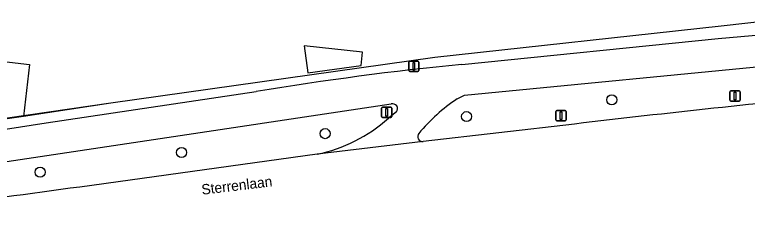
# Model space of a CAD drawing. Extents: x 162398 to 163643, y 386453 to 387397.
# Drawn here: x 163024.9 to 163096.1, y 386504.5 to 386525.7 of the extents above; entities that cross this region are included whole.
import ezdxf

# ---------------------------------------------------------------- set-up
doc = ezdxf.new("R2010")
doc.units = 0
for name, color, linetype in [('IMGEO_Boom', 7, 'Continuous'), ('IMGEO_Fietspad_gesloten', 7, 'Continuous'), ('IMGEO_Groenvoorziening', 7, 'Continuous'), ('IMGEO_Muur', 7, 'Continuous'), ('IMGEO_Openbare_ruimte_label', 7, 'Continuous'), ('IMGEO_Pand', 7, 'Continuous'), ('IMGEO_Rijbaan_regionaal_gesloten', 7, 'Continuous'), ('IMGEO_Verkeersbordpaal', 7, 'Continuous')]:
    doc.layers.add(name, color=color, linetype=linetype)

msp = doc.modelspace()

# ---------------------------------------------------------------- linework, layer by layer
at = {"layer": 'IMGEO_Boom'}
for centre in [(163082.944, 386517.469), (163068.839, 386515.839), (163055.088, 386514.185), (163041.148, 386512.357), (163027.399, 386510.439)]:
    msp.add_circle(centre, 0.489, dxfattribs=at)
at = {"layer": 'IMGEO_Fietspad_gesloten'}
for points in [[(163068.381, 386520.901), (163093.275, 386523.436), (163115.339, 386525.357)], [(163067.923, 386517.561), (163068.628, 386517.907), (163100.034, 386520.946), (163110.988, 386521.896)], [(162974.515, 386506.796), (162980.409, 386507.615), (163001.325, 386511.092), (163027.988, 386515.245), (163048.408, 386518.26)], [(162980.856, 386504.506), (162981.406, 386504.589), (162981.956, 386504.674), (163009.447, 386509.267), (163061.515, 386517.072)], [(163062.026, 386516.295), (163061.24, 386515.671)]]:
    msp.add_lwpolyline(points, dxfattribs=at)
for centre, radius, start, end in [((163096.399, 386232.165), 290.092, 95.54245, 99.52243), ((163078.016, 386502.57), 18.072, 123.95183, 139.90713), ((163061.642, 386516.599), 0.49, 321.66967, 104.99278), ((163051.071, 386527.234), 15.399, 282.18218, 311.33146), ((163064.576, 386513.908), 0.489, 141.9636, 273.8643)]:
    msp.add_arc(centre, radius, start, end, dxfattribs=at)
at = {"layer": 'IMGEO_Groenvoorziening'}
msp.add_lwpolyline([(163093.59, 386524.62), (163065.757, 386521.573), (163034.262, 386517.143), (163025.775, 386515.854)], dxfattribs=at)
msp.add_arc((163115.529, 386339.232), 186.681, 92.50635, 96.74894, dxfattribs=at)
at = {"layer": 'IMGEO_Muur'}
msp.add_lwpolyline([(163093.59, 386524.62), (163065.757, 386521.573), (163034.262, 386517.143), (162997.635, 386511.833), (162974.368, 386508.176)], dxfattribs=at)
msp.add_arc((163115.529, 386339.232), 186.681, 92.50635, 96.74894, dxfattribs=at)
at = {"layer": 'IMGEO_Pand'}
for points in [[(163053.068, 386522.724), (163053.427, 386520.095), (163058.589, 386520.815), (163058.732, 386522.092), (163053.068, 386522.724)], [(163018.062, 386514.753), (163018.871, 386521.771), (163026.358, 386520.908), (163025.775, 386515.854)], [(163025.775, 386515.854), (163018.062, 386514.753)]]:
    msp.add_lwpolyline(points, dxfattribs=at)
at = {"layer": 'IMGEO_Rijbaan_regionaal_gesloten'}
for points in [[(163079.34, 386515.118), (163064.609, 386513.42)], [(163064.609, 386513.42), (163054.32, 386512.182)], [(163054.32, 386512.182), (163031.252, 386509.003)]]:
    msp.add_lwpolyline(points, dxfattribs=at)
for centre, radius, start, end in [((163222.591, 385306.317), 1217.26, 95.478115, 96.758428), ((163203.567, 385220.017), 1300.453, 97.614313, 98.916261)]:
    msp.add_arc(centre, radius, start, end, dxfattribs=at)
at = {"layer": 'IMGEO_Verkeersbordpaal'}
for p, q in [((163063.22, 386520.328), (163063.22, 386521.128)), ((163063.22, 386521.128), (163063.22, 386520.328)), ((163063.32, 386521.228), (163064.11, 386521.228)), ((163064.11, 386521.228), (163063.32, 386521.228)), ((163064.21, 386521.128), (163064.21, 386520.328)), ((163064.21, 386520.328), (163064.21, 386521.128)), ((163064.11, 386520.228), (163063.32, 386520.228)), ((163063.32, 386520.228), (163064.11, 386520.228)), ((163094.429, 386517.433), (163094.429, 386518.233)), ((163094.429, 386518.233), (163094.429, 386517.433)), ((163094.529, 386518.333), (163095.319, 386518.333)), ((163095.319, 386518.333), (163094.529, 386518.333)), ((163095.419, 386518.233), (163095.419, 386517.433)), ((163095.419, 386517.433), (163095.419, 386518.233)), ((163095.319, 386517.333), (163094.529, 386517.333)), ((163094.529, 386517.333), (163095.319, 386517.333)), ((163060.581, 386515.851), (163060.581, 386516.651)), ((163060.581, 386516.651), (163060.581, 386515.851)), ((163060.681, 386516.751), (163061.471, 386516.751)), ((163061.471, 386516.751), (163060.681, 386516.751)), ((163061.571, 386516.651), (163061.571, 386515.851)), ((163061.571, 386515.851), (163061.571, 386516.651)), ((163077.517, 386515.53), (163077.517, 386516.33)), ((163077.517, 386516.33), (163077.517, 386515.53)), ((163077.617, 386516.43), (163078.407, 386516.43)), ((163078.407, 386516.43), (163077.617, 386516.43)), ((163078.507, 386516.33), (163078.507, 386515.53)), ((163078.507, 386515.53), (163078.507, 386516.33)), ((163061.471, 386515.751), (163060.681, 386515.751)), ((163060.681, 386515.751), (163061.471, 386515.751)), ((163078.407, 386515.43), (163077.617, 386515.43)), ((163077.617, 386515.43), (163078.407, 386515.43))]:
    msp.add_line(p, q, dxfattribs=at)
for points in [[(163063.64, 386521.103), (163063.79, 386521.103), (163063.79, 386520.353), (163063.64, 386520.353), (163063.64, 386521.103)], [(163094.849, 386518.208), (163094.999, 386518.208), (163094.999, 386517.458), (163094.849, 386517.458), (163094.849, 386518.208)], [(163061.001, 386516.626), (163061.151, 386516.626), (163061.151, 386515.876), (163061.001, 386515.876), (163061.001, 386516.626)], [(163077.937, 386516.305), (163078.087, 386516.305), (163078.087, 386515.555), (163077.937, 386515.555), (163077.937, 386516.305)]]:
    msp.add_lwpolyline(points, dxfattribs=at)
for centre, start, end in [((163063.32, 386521.128), 90, 180), ((163063.32, 386521.128), 90, 180), ((163064.11, 386521.128), 0, 90), ((163064.11, 386521.128), 360, 90), ((163063.32, 386520.328), 180, 270), ((163063.32, 386520.328), 180, 270), ((163064.11, 386520.328), 270, 0), ((163064.11, 386520.328), 270, 0), ((163094.529, 386518.233), 90, 180), ((163094.529, 386518.233), 90, 180), ((163095.319, 386518.233), 0, 90), ((163095.319, 386518.233), 360, 90), ((163094.529, 386517.433), 180, 270), ((163094.529, 386517.433), 180, 270), ((163095.319, 386517.433), 270, 0), ((163095.319, 386517.433), 270, 0), ((163060.681, 386516.651), 90, 180), ((163060.681, 386516.651), 90, 180), ((163061.471, 386516.651), 0, 90), ((163061.471, 386516.651), 360, 90), ((163077.617, 386516.33), 90, 180), ((163077.617, 386516.33), 90, 180), ((163078.407, 386516.33), 0, 90), ((163078.407, 386516.33), 360, 90), ((163060.681, 386515.851), 180, 270), ((163060.681, 386515.851), 180, 270), ((163061.471, 386515.851), 270, 0), ((163061.471, 386515.851), 270, 0), ((163077.617, 386515.53), 180, 270), ((163077.617, 386515.53), 180, 270), ((163078.407, 386515.53), 270, 0), ((163078.407, 386515.53), 270, 0)]:
    msp.add_arc(centre, 0.1, start, end, dxfattribs=at)

# ---------------------------------------------------------------- texts
at = {"layer": 'IMGEO_Openbare_ruimte_label'}
msp.add_text('Sterrenlaan', height=1, rotation=6.83367, dxfattribs=at).set_placement((163043.142, 386508.249))

doc.saveas('drawing.dxf')
